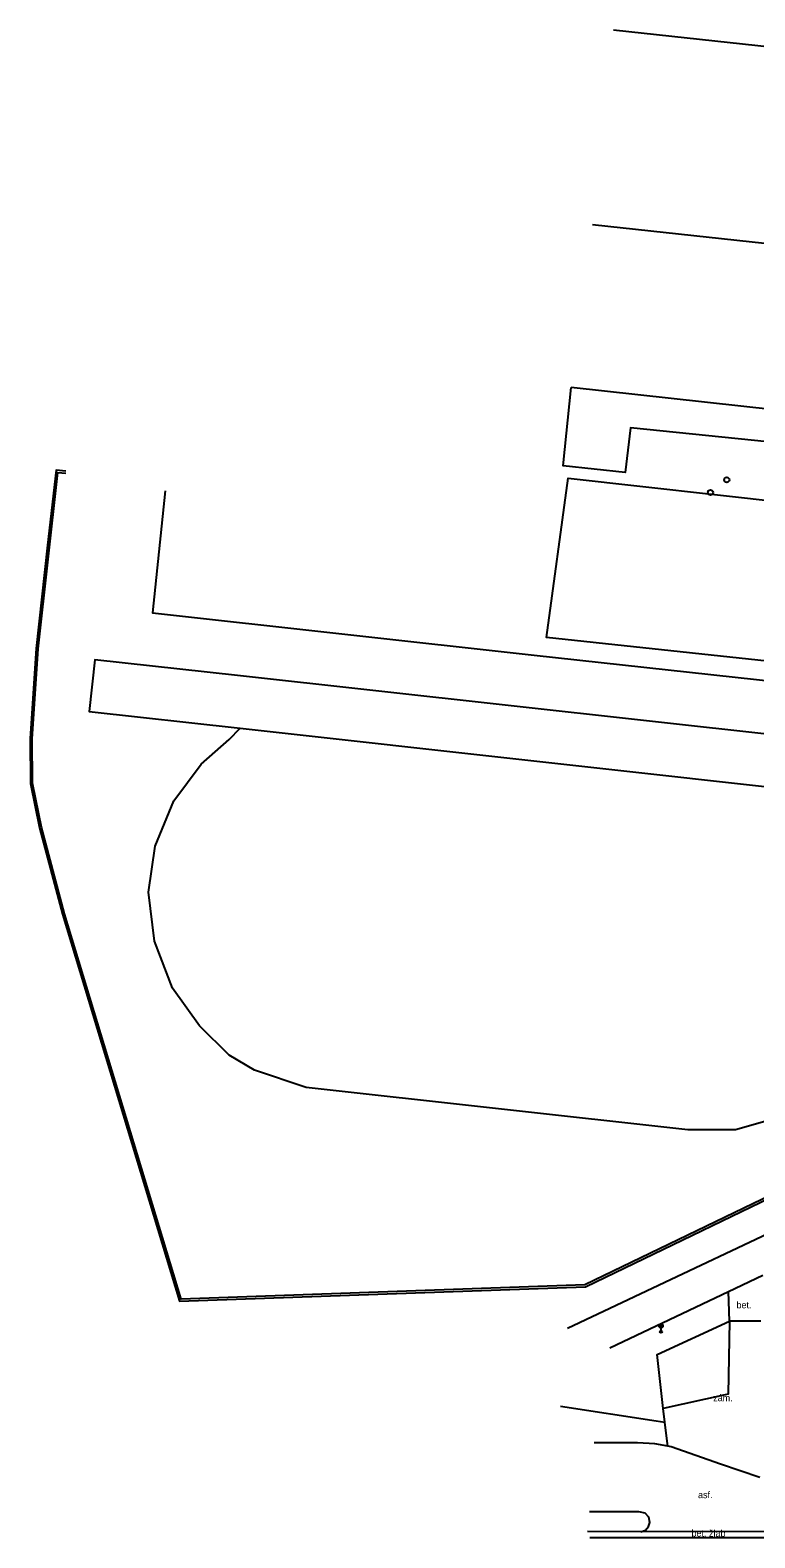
# Model space of a CAD drawing. Extents: x -602419 to -601554, y -1162937 to -1162362.
# Drawn here: x -602419.5 to -602349.4, y -1162714.8 to -1162568.9 of the extents above; entities that cross this region are included whole.
import ezdxf

# ---------------------------------------------------------------- set-up
doc = ezdxf.new("R2010")
doc.units = 0
doc.layers.add('Podklad', color=7, linetype='Continuous')

msp = doc.modelspace()

# ---------------------------------------------------------------- linework, layer by layer
at = {"layer": 'Podklad'}
for p, q in [((-602358.5925, -1162694.38), (-602358.3275, -1162694.115)), ((-602358.5925, -1162694.115), (-602358.3275, -1162694.38)), ((-602358.46, -1162694.435), (-602358.46, -1162694.81))]:
    msp.add_line(p, q, dxfattribs=at)
for points in [[(-602314.34, -1162574.17), (-602363.05, -1162568.87)], [(-602365.1, -1162587.6599), (-602316.38, -1162592.96)], [(-602318.2, -1162608.84), (-602319.03, -1162616.33), (-602325, -1162615.68), (-602324.53, -1162611.13), (-602339.45, -1162609.59), (-602339.9099, -1162614.08), (-602346.99, -1162613.31), (-602346.58, -1162608.86), (-602361.42, -1162607.34), (-602361.92, -1162611.68), (-602367.9099, -1162611.02), (-602367.1599, -1162603.46)], [(-602318.2, -1162608.84), (-602367.1599, -1162603.46)], [(-602416.01, -1162611.55), (-602416.9699, -1162611.44), (-602417.7801, -1162618.6899), (-602418.9, -1162628.71), (-602419.4699, -1162637.42), (-602419.45, -1162641.75), (-602418.58, -1162646.04), (-602416.34, -1162654.4099), (-602405.02, -1162691.86), (-602365.76, -1162690.46), (-602342.26, -1162679.12), (-602335.78, -1162673.36)], [(-602335.75, -1162673.15), (-602342.37, -1162678.95), (-602365.81, -1162690.27), (-602404.87, -1162691.6599), (-602416.14, -1162654.36), (-602418.38, -1162646), (-602419.25, -1162641.73), (-602419.27, -1162637.43), (-602418.7, -1162628.7199), (-602416.8, -1162611.6599), (-602416.03, -1162611.75)], [(-602333.18, -1162631.55), (-602369.52, -1162627.62), (-602367.45, -1162612.23), (-602346.07, -1162614.62), (-602319.53, -1162617.6), (-602318.86, -1162617.67), (-602320.74, -1162632.85), (-602321.78, -1162641.24)], [(-602406.42, -1162613.44), (-602407.63, -1162625.26), (-602370.74, -1162629.36), (-602336.25, -1162633.11), (-602333.45, -1162633.42)], [(-602334.24, -1162643.63), (-602333.7, -1162638.61), (-602399.43, -1162631.32), (-602413.2, -1162629.79), (-602413.76, -1162634.8), (-602399.17, -1162636.42), (-602340.91, -1162642.88), (-602336.16, -1162643.41)], [(-602340.91, -1162642.88), (-602338.17, -1162645.84), (-602336.71, -1162648.92), (-602335.81, -1162650.8), (-602334.91, -1162655.6), (-602335.55, -1162661.39), (-602338.33, -1162666.79), (-602341.98, -1162671), (-602347.06, -1162674.09), (-602351.26, -1162675.28), (-602355.87, -1162675.28), (-602392.78, -1162671.16), (-602397.78, -1162669.49), (-602400.24, -1162668.06), (-602403.1, -1162665.2), (-602405.72, -1162661.55), (-602407.46, -1162657.03), (-602408.02, -1162652.26), (-602407.38, -1162647.82), (-602405.56, -1162643.45), (-602402.94, -1162639.88), (-602400.24, -1162637.5), (-602399.17, -1162636.42)], [(-602338.7199, -1162680.89), (-602367.49, -1162694.49)], [(-602351.94, -1162690.9099), (-602348.62, -1162689.33)], [(-602363.4099, -1162696.36), (-602351.94, -1162690.9099)], [(-602351.84, -1162693.8), (-602351.94, -1162690.9099)], [(-602358.1, -1162703.56), (-602358.25, -1162702.22), (-602358.84, -1162697.02), (-602351.84, -1162693.8)], [(-602358.1, -1162703.56), (-602358.25, -1162702.22), (-602358.84, -1162697.02), (-602351.84, -1162693.8)], [(-602351.84, -1162693.8), (-602351.95, -1162700.84), (-602352.24, -1162700.91), (-602358.25, -1162702.22)], [(-602348.81, -1162693.8), (-602351.84, -1162693.8)], [(-602368.17, -1162702), (-602358.93, -1162703.43)], [(-602368.17, -1162702), (-602358.93, -1162703.43)], [(-602358.93, -1162703.43), (-602358.1, -1162703.56)], [(-602357.81, -1162705.87), (-602358.03, -1162704.09), (-602358.1, -1162703.56)], [(-602357.81, -1162705.87), (-602359.05, -1162705.64), (-602360.73, -1162705.55), (-602364.9099, -1162705.55)], [(-602357.4699, -1162705.93), (-602357.81, -1162705.87)], [(-602352.7, -1162707.61), (-602357.4699, -1162705.93)], [(-602348.9099, -1162708.92), (-602352.7, -1162707.61)], [(-602360.4099, -1162714.1599), (-602359.9699, -1162714), (-602359.6599, -1162713.6599), (-602359.54, -1162713.25), (-602359.64, -1162712.75), (-602360, -1162712.36), (-602360.61, -1162712.2199), (-602365.39, -1162712.2199)], [(-602360.4099, -1162714.1599), (-602365.58, -1162714.12)], [(-602347.82, -1162714.15), (-602360.4099, -1162714.1599)], [(-602347.82, -1162714.75), (-602365.34, -1162714.75)]]:
    msp.add_lwpolyline(points, dxfattribs=at)
for centre, radius in [((-602352.1, -1162612.38), 0.25), ((-602353.68, -1162613.6), 0.25), ((-602358.46, -1162694.2475), 0.1875), ((-602358.46, -1162694.81), 0.1), ((-602358.46, -1162694.81), 0.0723), ((-602358.46, -1162694.81), 0.0438)]:
    msp.add_circle(centre, radius, dxfattribs=at)

# ---------------------------------------------------------------- texts
for s, p in [('bet.', (-602351.1599, -1162692.54)), ('zám.', (-602353.4099, -1162701.53)), (' asf.', (-602355.12, -1162710.9099))]:
    msp.add_text(s, height=0.65, dxfattribs=at).set_placement(p)
msp.add_text('bet. žlab', height=0.65, rotation=359.68, dxfattribs=at).set_placement((-602355.51, -1162714.62))

doc.saveas('drawing.dxf')
